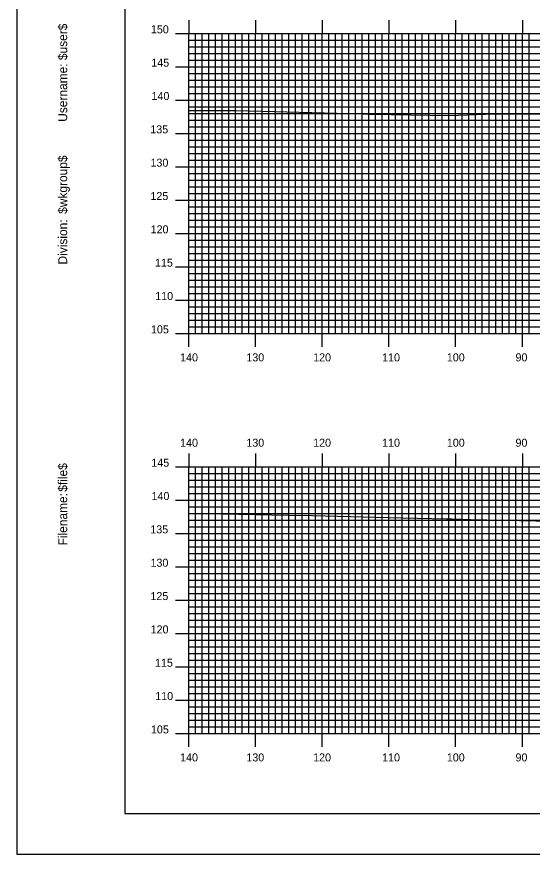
# Model space of a CAD drawing. Extents: x 1768874 to 1769217, y 442591 to 442811.
# Drawn here: x 1768874.2 to 1768951.5, y 442590.5 to 442716.2 of the extents above; entities that cross this region are included whole.
import ezdxf

# ---------------------------------------------------------------- set-up
doc = ezdxf.new("R2010")
doc.units = 0
for name, color, linetype in [('BORDER', 7, 'Continuous'), ('H_V ANNOTATION', 7, 'Continuous'), ('MAJOR', 7, 'Continuous'), ('MINOR', 7, 'Continuous'), ('PLOT BOUNDARY', 7, 'Continuous'), ('S_Roadway_Centerline', 7, 'Continuous')]:
    doc.layers.add(name, color=color, linetype=linetype)

msp = doc.modelspace()

# ---------------------------------------------------------------- linework, layer by layer
at = {"layer": 'BORDER'}
msp.add_lwpolyline([(1768890.39, 442596.67), (1769210.39, 442596.67), (1769210.39, 442806.67), (1768890.39, 442806.67)], close=True, dxfattribs=at)
at = {"layer": 'MAJOR'}
for p, q in [((1768899.99, 442715.67), (1768899.99, 442713.67)), ((1768909.99, 442715.67), (1768909.99, 442713.67)), ((1768919.99, 442715.67), (1768919.99, 442713.67)), ((1768929.99, 442715.67), (1768929.99, 442713.67)), ((1768939.99, 442715.67), (1768939.99, 442713.67)), ((1768949.99, 442715.67), (1768949.99, 442713.67)), ((1768897.98, 442713.67), (1768899.99, 442713.67)), ((1768899.99, 442713.67), (1769179.99, 442713.67)), ((1768899.99, 442668.67), (1768899.99, 442713.67)), ((1768899.99, 442668.67), (1768899.99, 442713.67)), ((1768899.99, 442713.67), (1769179.99, 442713.67)), ((1768909.99, 442668.67), (1768909.99, 442713.67)), ((1768919.99, 442668.67), (1768919.99, 442713.67)), ((1768929.99, 442668.67), (1768929.99, 442713.67)), ((1768939.99, 442668.67), (1768939.99, 442713.67)), ((1768949.99, 442668.67), (1768949.99, 442713.67)), ((1768897.98, 442708.67), (1768899.99, 442708.67)), ((1768899.99, 442708.67), (1769179.99, 442708.67)), ((1768897.98, 442703.67), (1768899.99, 442703.67)), ((1768899.99, 442703.67), (1769179.99, 442703.67)), ((1768897.98, 442698.67), (1768899.99, 442698.67)), ((1768899.99, 442698.67), (1769179.99, 442698.67)), ((1768897.98, 442693.67), (1768899.99, 442693.67)), ((1768899.99, 442693.67), (1769179.99, 442693.67)), ((1768897.98, 442688.67), (1768899.99, 442688.67)), ((1768899.99, 442688.67), (1769179.99, 442688.67)), ((1768897.98, 442683.67), (1768899.99, 442683.67)), ((1768899.99, 442683.67), (1769179.99, 442683.67)), ((1768897.98, 442678.67), (1768899.99, 442678.67)), ((1768899.99, 442678.67), (1769179.99, 442678.67)), ((1768897.98, 442673.67), (1768899.99, 442673.67)), ((1768899.99, 442673.67), (1769179.99, 442673.67)), ((1768897.98, 442668.67), (1768899.99, 442668.67)), ((1768899.99, 442668.67), (1769179.99, 442668.67)), ((1768899.99, 442668.67), (1769179.99, 442668.67)), ((1768899.99, 442666.66), (1768899.99, 442668.67)), ((1768909.99, 442666.66), (1768909.99, 442668.67)), ((1768919.99, 442666.66), (1768919.99, 442668.67)), ((1768929.99, 442666.66), (1768929.99, 442668.67)), ((1768939.99, 442666.66), (1768939.99, 442668.67)), ((1768949.99, 442666.66), (1768949.99, 442668.67)), ((1768899.99, 442650.67), (1768899.99, 442648.67)), ((1768909.99, 442650.67), (1768909.99, 442648.67)), ((1768919.99, 442650.67), (1768919.99, 442648.67)), ((1768929.99, 442650.67), (1768929.99, 442648.67)), ((1768939.99, 442650.67), (1768939.99, 442648.67)), ((1768949.99, 442650.67), (1768949.99, 442648.67)), ((1768897.98, 442648.67), (1768899.99, 442648.67)), ((1768899.99, 442648.67), (1769179.99, 442648.67)), ((1768899.99, 442608.67), (1768899.99, 442648.67)), ((1768899.99, 442608.67), (1768899.99, 442648.67)), ((1768899.99, 442648.67), (1769179.99, 442648.67)), ((1768909.99, 442608.67), (1768909.99, 442648.67)), ((1768919.99, 442608.67), (1768919.99, 442648.67)), ((1768929.99, 442608.67), (1768929.99, 442648.67)), ((1768939.99, 442608.67), (1768939.99, 442648.67)), ((1768949.99, 442608.67), (1768949.99, 442648.67)), ((1768897.98, 442643.67), (1768899.99, 442643.67)), ((1768899.99, 442643.67), (1769179.99, 442643.67)), ((1768897.98, 442638.67), (1768899.99, 442638.67)), ((1768899.99, 442638.67), (1769179.99, 442638.67)), ((1768897.98, 442633.67), (1768899.99, 442633.67)), ((1768899.99, 442633.67), (1769179.99, 442633.67)), ((1768897.98, 442628.67), (1768899.99, 442628.67)), ((1768899.99, 442628.67), (1769179.99, 442628.67)), ((1768897.98, 442623.67), (1768899.99, 442623.67)), ((1768899.99, 442623.67), (1769179.99, 442623.67)), ((1768897.98, 442618.67), (1768899.99, 442618.67)), ((1768899.99, 442618.67), (1769179.99, 442618.67)), ((1768897.98, 442613.67), (1768899.99, 442613.67)), ((1768899.99, 442613.67), (1769179.99, 442613.67)), ((1768897.98, 442608.67), (1768899.99, 442608.67)), ((1768899.99, 442608.67), (1769179.99, 442608.67)), ((1768899.99, 442608.67), (1769179.99, 442608.67)), ((1768899.99, 442606.66), (1768899.99, 442608.67)), ((1768909.99, 442606.66), (1768909.99, 442608.67)), ((1768919.99, 442606.66), (1768919.99, 442608.67)), ((1768929.99, 442606.66), (1768929.99, 442608.67)), ((1768939.99, 442606.66), (1768939.99, 442608.67)), ((1768949.99, 442606.66), (1768949.99, 442608.67))]:
    msp.add_line(p, q, dxfattribs=at)
at = {"layer": 'MINOR'}
for p, q in [((1768900.99, 442668.67), (1768900.99, 442713.67)), ((1768901.99, 442668.67), (1768901.99, 442713.67)), ((1768902.99, 442668.67), (1768902.99, 442713.67)), ((1768903.99, 442668.67), (1768903.99, 442713.67)), ((1768904.99, 442668.67), (1768904.99, 442713.67)), ((1768905.99, 442668.67), (1768905.99, 442713.67)), ((1768906.99, 442668.67), (1768906.99, 442713.67)), ((1768907.99, 442668.67), (1768907.99, 442713.67)), ((1768908.99, 442668.67), (1768908.99, 442713.67)), ((1768910.99, 442668.67), (1768910.99, 442713.67)), ((1768911.99, 442668.67), (1768911.99, 442713.67)), ((1768912.99, 442668.67), (1768912.99, 442713.67)), ((1768913.99, 442668.67), (1768913.99, 442713.67)), ((1768914.99, 442668.67), (1768914.99, 442713.67)), ((1768915.99, 442668.67), (1768915.99, 442713.67)), ((1768916.99, 442668.67), (1768916.99, 442713.67)), ((1768917.99, 442668.67), (1768917.99, 442713.67)), ((1768918.99, 442668.67), (1768918.99, 442713.67)), ((1768920.99, 442668.67), (1768920.99, 442713.67)), ((1768921.99, 442668.67), (1768921.99, 442713.67)), ((1768922.99, 442668.67), (1768922.99, 442713.67)), ((1768923.99, 442668.67), (1768923.99, 442713.67)), ((1768924.99, 442668.67), (1768924.99, 442713.67)), ((1768925.99, 442668.67), (1768925.99, 442713.67)), ((1768926.99, 442668.67), (1768926.99, 442713.67)), ((1768927.99, 442668.67), (1768927.99, 442713.67)), ((1768928.99, 442668.67), (1768928.99, 442713.67)), ((1768930.99, 442668.67), (1768930.99, 442713.67)), ((1768931.99, 442668.67), (1768931.99, 442713.67)), ((1768932.99, 442668.67), (1768932.99, 442713.67)), ((1768933.99, 442668.67), (1768933.99, 442713.67)), ((1768934.99, 442668.67), (1768934.99, 442713.67)), ((1768935.99, 442668.67), (1768935.99, 442713.67)), ((1768936.99, 442668.67), (1768936.99, 442713.67)), ((1768937.99, 442668.67), (1768937.99, 442713.67)), ((1768938.99, 442668.67), (1768938.99, 442713.67)), ((1768940.99, 442668.67), (1768940.99, 442713.67)), ((1768941.99, 442668.67), (1768941.99, 442713.67)), ((1768942.99, 442668.67), (1768942.99, 442713.67)), ((1768943.99, 442668.67), (1768943.99, 442713.67)), ((1768944.99, 442668.67), (1768944.99, 442713.67)), ((1768945.99, 442668.67), (1768945.99, 442713.67)), ((1768946.99, 442668.67), (1768946.99, 442713.67)), ((1768947.99, 442668.67), (1768947.99, 442713.67)), ((1768948.99, 442668.67), (1768948.99, 442713.67)), ((1768950.99, 442668.67), (1768950.99, 442713.67)), ((1768899.99, 442712.67), (1769179.99, 442712.67)), ((1768899.99, 442712.67), (1768901.99, 442712.67)), ((1768899.99, 442711.67), (1769179.99, 442711.67)), ((1768899.99, 442711.67), (1768901.99, 442711.67)), ((1768899.99, 442710.67), (1769179.99, 442710.67)), ((1768899.99, 442710.67), (1768901.99, 442710.67)), ((1768899.99, 442709.67), (1769179.99, 442709.67)), ((1768899.99, 442709.67), (1768901.99, 442709.67)), ((1768899.99, 442707.67), (1769179.99, 442707.67)), ((1768899.99, 442707.67), (1768901.99, 442707.67)), ((1768899.99, 442706.67), (1769179.99, 442706.67)), ((1768899.99, 442706.67), (1768901.99, 442706.67)), ((1768899.99, 442705.67), (1769179.99, 442705.67)), ((1768899.99, 442705.67), (1768901.99, 442705.67)), ((1768899.99, 442704.67), (1769179.99, 442704.67)), ((1768899.99, 442704.67), (1768901.99, 442704.67)), ((1768899.99, 442702.67), (1769179.99, 442702.67)), ((1768899.99, 442702.67), (1768901.99, 442702.67)), ((1768899.99, 442701.67), (1769179.99, 442701.67)), ((1768899.99, 442701.67), (1768901.99, 442701.67)), ((1768899.99, 442700.67), (1769179.99, 442700.67)), ((1768899.99, 442700.67), (1768901.99, 442700.67)), ((1768899.99, 442699.67), (1769179.99, 442699.67)), ((1768899.99, 442699.67), (1768901.99, 442699.67)), ((1768899.99, 442697.67), (1769179.99, 442697.67)), ((1768899.99, 442697.67), (1768901.99, 442697.67)), ((1768899.99, 442696.67), (1769179.99, 442696.67)), ((1768899.99, 442696.67), (1768901.99, 442696.67)), ((1768899.99, 442695.67), (1769179.99, 442695.67)), ((1768899.99, 442695.67), (1768901.99, 442695.67)), ((1768899.99, 442694.67), (1769179.99, 442694.67)), ((1768899.99, 442694.67), (1768901.99, 442694.67)), ((1768899.99, 442692.67), (1769179.99, 442692.67)), ((1768899.99, 442692.67), (1768901.99, 442692.67)), ((1768899.99, 442691.67), (1769179.99, 442691.67)), ((1768899.99, 442691.67), (1768901.99, 442691.67)), ((1768899.99, 442690.67), (1769179.99, 442690.67)), ((1768899.99, 442690.67), (1768901.99, 442690.67)), ((1768899.99, 442689.67), (1769179.99, 442689.67)), ((1768899.99, 442689.67), (1768901.99, 442689.67)), ((1768899.99, 442687.67), (1769179.99, 442687.67)), ((1768899.99, 442687.67), (1768901.99, 442687.67)), ((1768899.99, 442686.67), (1769179.99, 442686.67)), ((1768899.99, 442686.67), (1768901.99, 442686.67)), ((1768899.99, 442685.67), (1769179.99, 442685.67)), ((1768899.99, 442685.67), (1768901.99, 442685.67)), ((1768899.99, 442684.67), (1769179.99, 442684.67)), ((1768899.99, 442684.67), (1768901.99, 442684.67)), ((1768899.99, 442682.67), (1769179.99, 442682.67)), ((1768899.99, 442682.67), (1768901.99, 442682.67)), ((1768899.99, 442681.67), (1769179.99, 442681.67)), ((1768899.99, 442681.67), (1768901.99, 442681.67)), ((1768899.99, 442680.67), (1769179.99, 442680.67)), ((1768899.99, 442680.67), (1768901.99, 442680.67)), ((1768899.99, 442679.67), (1769179.99, 442679.67)), ((1768899.99, 442679.67), (1768901.99, 442679.67)), ((1768899.99, 442677.67), (1769179.99, 442677.67)), ((1768899.99, 442677.67), (1768901.99, 442677.67)), ((1768899.99, 442676.67), (1769179.99, 442676.67)), ((1768899.99, 442676.67), (1768901.99, 442676.67)), ((1768899.99, 442675.67), (1769179.99, 442675.67)), ((1768899.99, 442675.67), (1768901.99, 442675.67)), ((1768899.99, 442674.67), (1769179.99, 442674.67)), ((1768899.99, 442674.67), (1768901.99, 442674.67)), ((1768899.99, 442672.67), (1769179.99, 442672.67)), ((1768899.99, 442672.67), (1768901.99, 442672.67)), ((1768899.99, 442671.67), (1769179.99, 442671.67)), ((1768899.99, 442671.67), (1768901.99, 442671.67)), ((1768899.99, 442670.67), (1769179.99, 442670.67)), ((1768899.99, 442670.67), (1768901.99, 442670.67)), ((1768899.99, 442669.67), (1769179.99, 442669.67)), ((1768899.99, 442669.67), (1768901.99, 442669.67)), ((1768900.99, 442608.67), (1768900.99, 442648.67)), ((1768901.99, 442608.67), (1768901.99, 442648.67)), ((1768902.99, 442608.67), (1768902.99, 442648.67)), ((1768903.99, 442608.67), (1768903.99, 442648.67)), ((1768904.99, 442608.67), (1768904.99, 442648.67)), ((1768905.99, 442608.67), (1768905.99, 442648.67)), ((1768906.99, 442608.67), (1768906.99, 442648.67)), ((1768907.99, 442608.67), (1768907.99, 442648.67)), ((1768908.99, 442608.67), (1768908.99, 442648.67)), ((1768910.99, 442608.67), (1768910.99, 442648.67)), ((1768911.99, 442608.67), (1768911.99, 442648.67)), ((1768912.99, 442608.67), (1768912.99, 442648.67)), ((1768913.99, 442608.67), (1768913.99, 442648.67)), ((1768914.99, 442608.67), (1768914.99, 442648.67)), ((1768915.99, 442608.67), (1768915.99, 442648.67)), ((1768916.99, 442608.67), (1768916.99, 442648.67)), ((1768917.99, 442608.67), (1768917.99, 442648.67)), ((1768918.99, 442608.67), (1768918.99, 442648.67)), ((1768920.99, 442608.67), (1768920.99, 442648.67)), ((1768921.99, 442608.67), (1768921.99, 442648.67)), ((1768922.99, 442608.67), (1768922.99, 442648.67)), ((1768923.99, 442608.67), (1768923.99, 442648.67)), ((1768924.99, 442608.67), (1768924.99, 442648.67)), ((1768925.99, 442608.67), (1768925.99, 442648.67)), ((1768926.99, 442608.67), (1768926.99, 442648.67)), ((1768927.99, 442608.67), (1768927.99, 442648.67)), ((1768928.99, 442608.67), (1768928.99, 442648.67)), ((1768930.99, 442608.67), (1768930.99, 442648.67)), ((1768931.99, 442608.67), (1768931.99, 442648.67)), ((1768932.99, 442608.67), (1768932.99, 442648.67)), ((1768933.99, 442608.67), (1768933.99, 442648.67)), ((1768934.99, 442608.67), (1768934.99, 442648.67)), ((1768935.99, 442608.67), (1768935.99, 442648.67)), ((1768936.99, 442608.67), (1768936.99, 442648.67)), ((1768937.99, 442608.67), (1768937.99, 442648.67)), ((1768938.99, 442608.67), (1768938.99, 442648.67)), ((1768940.99, 442608.67), (1768940.99, 442648.67)), ((1768941.99, 442608.67), (1768941.99, 442648.67)), ((1768942.99, 442608.67), (1768942.99, 442648.67)), ((1768943.99, 442608.67), (1768943.99, 442648.67)), ((1768944.99, 442608.67), (1768944.99, 442648.67)), ((1768945.99, 442608.67), (1768945.99, 442648.67)), ((1768946.99, 442608.67), (1768946.99, 442648.67)), ((1768947.99, 442608.67), (1768947.99, 442648.67)), ((1768948.99, 442608.67), (1768948.99, 442648.67)), ((1768950.99, 442608.67), (1768950.99, 442648.67)), ((1768899.99, 442647.67), (1769179.99, 442647.67)), ((1768899.99, 442647.67), (1768901.99, 442647.67)), ((1768899.99, 442646.67), (1769179.99, 442646.67)), ((1768899.99, 442646.67), (1768901.99, 442646.67)), ((1768899.99, 442645.67), (1769179.99, 442645.67)), ((1768899.99, 442645.67), (1768901.99, 442645.67)), ((1768899.99, 442644.67), (1769179.99, 442644.67)), ((1768899.99, 442644.67), (1768901.99, 442644.67)), ((1768899.99, 442642.67), (1769179.99, 442642.67)), ((1768899.99, 442642.67), (1768901.99, 442642.67)), ((1768899.99, 442641.67), (1769179.99, 442641.67)), ((1768899.99, 442641.67), (1768901.99, 442641.67)), ((1768899.99, 442640.67), (1769179.99, 442640.67)), ((1768899.99, 442640.67), (1768901.99, 442640.67)), ((1768899.99, 442639.67), (1769179.99, 442639.67)), ((1768899.99, 442639.67), (1768901.99, 442639.67)), ((1768899.99, 442637.67), (1769179.99, 442637.67)), ((1768899.99, 442637.67), (1768901.99, 442637.67)), ((1768899.99, 442636.67), (1769179.99, 442636.67)), ((1768899.99, 442636.67), (1768901.99, 442636.67)), ((1768899.99, 442635.67), (1769179.99, 442635.67)), ((1768899.99, 442635.67), (1768901.99, 442635.67)), ((1768899.99, 442634.67), (1769179.99, 442634.67)), ((1768899.99, 442634.67), (1768901.99, 442634.67)), ((1768899.99, 442632.67), (1769179.99, 442632.67)), ((1768899.99, 442632.67), (1768901.99, 442632.67)), ((1768899.99, 442631.67), (1769179.99, 442631.67)), ((1768899.99, 442631.67), (1768901.99, 442631.67)), ((1768899.99, 442630.67), (1769179.99, 442630.67)), ((1768899.99, 442630.67), (1768901.99, 442630.67)), ((1768899.99, 442629.67), (1769179.99, 442629.67)), ((1768899.99, 442629.67), (1768901.99, 442629.67)), ((1768899.99, 442627.67), (1769179.99, 442627.67)), ((1768899.99, 442627.67), (1768901.99, 442627.67)), ((1768899.99, 442626.67), (1769179.99, 442626.67)), ((1768899.99, 442626.67), (1768901.99, 442626.67)), ((1768899.99, 442625.67), (1769179.99, 442625.67)), ((1768899.99, 442625.67), (1768901.99, 442625.67)), ((1768899.99, 442624.67), (1769179.99, 442624.67)), ((1768899.99, 442624.67), (1768901.99, 442624.67)), ((1768899.99, 442622.67), (1769179.99, 442622.67)), ((1768899.99, 442622.67), (1768901.99, 442622.67)), ((1768899.99, 442621.67), (1769179.99, 442621.67)), ((1768899.99, 442621.67), (1768901.99, 442621.67)), ((1768899.99, 442620.67), (1769179.99, 442620.67)), ((1768899.99, 442620.67), (1768901.99, 442620.67)), ((1768899.99, 442619.67), (1769179.99, 442619.67)), ((1768899.99, 442619.67), (1768901.99, 442619.67)), ((1768899.99, 442617.67), (1769179.99, 442617.67)), ((1768899.99, 442617.67), (1768901.99, 442617.67)), ((1768899.99, 442616.67), (1769179.99, 442616.67)), ((1768899.99, 442616.67), (1768901.99, 442616.67)), ((1768899.99, 442615.67), (1769179.99, 442615.67)), ((1768899.99, 442615.67), (1768901.99, 442615.67)), ((1768899.99, 442614.67), (1769179.99, 442614.67)), ((1768899.99, 442614.67), (1768901.99, 442614.67)), ((1768899.99, 442612.67), (1769179.99, 442612.67)), ((1768899.99, 442612.67), (1768901.99, 442612.67)), ((1768899.99, 442611.67), (1769179.99, 442611.67)), ((1768899.99, 442611.67), (1768901.99, 442611.67)), ((1768899.99, 442610.67), (1769179.99, 442610.67)), ((1768899.99, 442610.67), (1768901.99, 442610.67)), ((1768899.99, 442609.67), (1769179.99, 442609.67)), ((1768899.99, 442609.67), (1768901.99, 442609.67))]:
    msp.add_line(p, q, dxfattribs=at)
at = {"layer": 'PLOT BOUNDARY'}
msp.add_lwpolyline([(1768874.2, 442590.55), (1769214.2, 442590.55), (1769214.2, 442810.55), (1768874.2, 442810.55)], close=True, dxfattribs=at)
at = {"layer": 'S_Roadway_Centerline'}
for points in [[(1768899.99, 442702.09), (1768907.08, 442702.08), (1768926.03, 442701.58), (1768926.92, 442701.56), (1768927.11, 442701.55), (1768927.39, 442701.55), (1768939.09, 442701.36), (1768945.8, 442701.58), (1768962.04, 442701.59)], [(1768899.99, 442641.68), (1768914.87, 442641.42), (1768918.51, 442641.37), (1768929.92, 442641.03), (1768938.61, 442640.84), (1768939.42, 442640.83), (1768942.2, 442640.75), (1768956.92, 442640.43), (1768974.05, 442641.14), (1768975.57, 442641.23), (1768976.29, 442641.22), (1768987.05, 442641.38), (1768995.55, 442641.59), (1769004.68, 442641.73), (1769013.89, 442641.95), (1769022.99, 442642.2), (1769033.25, 442642.37), (1769046.24, 442642.48), (1769052.18, 442642.48), (1769057.97, 442642.53), (1769069.58, 442642.66), (1769071.5, 442642.66)]]:
    msp.add_lwpolyline(points, dxfattribs=at)

# ---------------------------------------------------------------- texts
at = {"layer": 'BORDER'}
for s, p in [('$user$', (1768881.76, 442709.65)), ('Username:', (1768881.76, 442700.4)), ('$wkgroup$', (1768881.76, 442686.6)), ('Division:', (1768881.76, 442679)), ('$file$', (1768881.76, 442644.92)), ('Filename:', (1768881.76, 442636.86))]:
    msp.add_text(s, height=1.339, rotation=90, dxfattribs=at).set_placement(p)
at = {"layer": 'H_V ANNOTATION'}
for s, p in [('150', (1768894.31, 442713.67)), ('145', (1768894.37, 442708.67)), ('140', (1768894.4, 442703.67)), ('135', (1768894.22, 442698.67)), ('130', (1768894.25, 442693.67)), ('125', (1768894.24, 442688.67)), ('120', (1768894.27, 442683.67)), ('115', (1768894.92, 442678.67)), ('110', (1768894.96, 442673.67)), ('105', (1768894.32, 442668.67)), ('140', (1768898.69, 442664.47)), ('130', (1768908.62, 442664.47)), ('120', (1768918.63, 442664.47)), ('110', (1768928.97, 442664.47)), ('100', (1768938.67, 442664.47)), ('90', (1768948.96, 442664.47)), ('140', (1768898.69, 442651.67)), ('130', (1768908.62, 442651.67)), ('120', (1768918.63, 442651.67)), ('110', (1768928.97, 442651.67)), ('100', (1768938.67, 442651.67)), ('90', (1768948.96, 442651.67)), ('145', (1768894.37, 442648.67)), ('140', (1768894.4, 442643.67)), ('135', (1768894.22, 442638.67)), ('130', (1768894.25, 442633.67)), ('125', (1768894.24, 442628.67)), ('120', (1768894.27, 442623.67)), ('115', (1768894.92, 442618.67)), ('110', (1768894.96, 442613.67)), ('105', (1768894.32, 442608.67)), ('140', (1768898.69, 442604.47)), ('130', (1768908.62, 442604.47)), ('120', (1768918.63, 442604.47)), ('110', (1768928.97, 442604.47)), ('100', (1768938.67, 442604.47)), ('90', (1768948.96, 442604.47))]:
    msp.add_text(s, height=1.2, dxfattribs=at).set_placement(p)
at = {"layer": 'MAJOR'}
for p in [(1768899.98, 442668.67), (1768899.98, 442608.67)]:
    msp.add_text('-', height=0.012, dxfattribs=at).set_placement(p)

doc.saveas('drawing.dxf')
